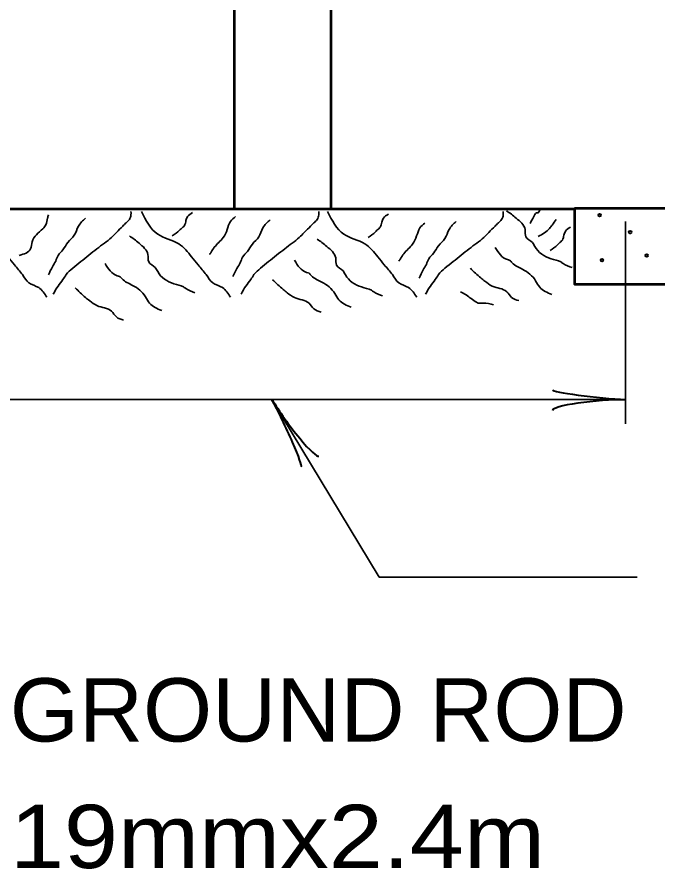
# Model space of a CAD drawing. Extents: x 14808 to 15663, y 10944 to 11488.
# Drawn here: x 14967.94 to 14998.34, y 11241.7 to 11282.09 of the extents above; entities that cross this region are included whole.
import ezdxf

# ---------------------------------------------------------------- set-up
doc = ezdxf.new("R2010")
doc.units = 0
doc.header["$LTSCALE"] = 1.2
doc.layers.add('1', color=7, linetype='Continuous', lineweight=53)

msp = doc.modelspace()

# ---------------------------------------------------------------- linework, layer by layer
at = {"layer": '1'}
for p, q in [((14978.258, 11273.001), (14978.258, 11294.621)), ((14982.845, 11273.001), (14982.845, 11294.621)), ((14963.259, 11273.001), (14994.385, 11273.001))]:
    msp.add_line(p, q, dxfattribs=at)
at = {"layer": '1', "lineweight": 35}
for p, q in [((14996.793, 11272.402), (14996.793, 11262.802)), ((14996.793, 11263.956), (14963.259, 11263.956))]:
    msp.add_line(p, q, dxfattribs=at)
at = {"layer": '1'}
for points in [[(14994.385, 11273.024), (15144.385, 11273.024), (15144.385, 11276.623), (15179.229, 11276.623)], [(14994.385, 11273.001), (14994.385, 11269.424), (15147.085, 11269.424), (15147.085, 11276.623)]]:
    msp.add_lwpolyline(points, dxfattribs=at)
at = {"layer": '1', "lineweight": 35}
msp.add_lwpolyline([(14980.026, 11263.956), (14985.125, 11255.533), (14997.359, 11255.533)], dxfattribs=at)
at = {"layer": '1', "lineweight": 40}
for centre in [(14995.572, 11272.697), (14997.022, 11271.892), (14995.689, 11270.559), (14997.805, 11270.781)]:
    msp.add_circle(centre, 0.06, dxfattribs=at)
for centre, major_axis, ratio, start_param, end_param in [((14995.449, 11264.21), (2.108, -0.211), 0.07063, 3.140715, 5.41811), ((14980.505, 11262.674), (-0.911, 1.912), 0.07063, 3.140715, 5.41811), ((14980.988, 11263.008), (-1.27, 1.736), 0.122415, 0.896353, 3.141593), ((14995.484, 11263.624), (2.143, 0.187), 0.122415, 0.896353, 3.141593)]:
    msp.add_ellipse(centre, major_axis=major_axis, ratio=ratio, start_param=start_param, end_param=end_param, dxfattribs=at)
at = {"layer": '1', "lineweight": 35}
for points in [[(14965.13, 11272.868), (14965.898, 11271.793), (14966.896, 11271.332), (14967.51, 11270.718), (14967.817, 11270.334), (14968.201, 11269.874), (14968.508, 11269.49), (14968.969, 11269.26), (14969.353, 11268.799)], [(14968.047, 11270.786), (14968.585, 11271.093), (14968.662, 11271.438), (14969.161, 11272.052), (14969.314, 11272.244), (14969.391, 11272.552), (14969.429, 11272.705)], [(14973.345, 11272.868), (14973.345, 11272.714), (14973.268, 11272.484), (14973.114, 11272.33), (14972.961, 11272.177), (14972.654, 11271.87), (14972.423, 11271.639), (14971.732, 11271.102), (14971.349, 11270.795), (14970.581, 11270.181), (14970.274, 11269.874), (14970.12, 11269.643), (14969.89, 11269.336), (14969.66, 11268.952)], [(14973.844, 11272.868), (14974.612, 11271.793), (14975.61, 11271.332), (14976.224, 11270.718), (14976.531, 11270.334), (14976.915, 11269.874), (14977.222, 11269.49), (14977.683, 11269.26), (14978.067, 11268.799)], [(14976.262, 11272.82), (14976.032, 11272.628), (14975.955, 11272.436), (14975.878, 11272.206), (14975.725, 11272.052), (14975.648, 11271.976), (14975.302, 11271.707)], [(14978.297, 11272.628), (14978.066, 11272.398), (14977.913, 11272.014), (14977.721, 11271.63), (14977.299, 11271.17), (14977.145, 11270.939), (14977.068, 11270.824)], [(14982.251, 11272.868), (14982.251, 11272.714), (14982.174, 11272.484), (14982.02, 11272.33), (14981.867, 11272.177), (14981.56, 11271.87), (14981.329, 11271.639), (14980.638, 11271.102), (14980.255, 11270.795), (14979.487, 11270.181), (14979.18, 11269.874), (14979.026, 11269.643), (14978.796, 11269.336), (14978.566, 11268.952)], [(14982.673, 11272.868), (14983.441, 11271.793), (14984.439, 11271.332), (14985.053, 11270.718), (14985.36, 11270.334), (14985.744, 11269.874), (14986.051, 11269.49), (14986.512, 11269.26), (14986.896, 11268.799)], [(14985.552, 11272.744), (14985.322, 11272.552), (14985.245, 11272.36), (14985.168, 11272.129), (14985.014, 11271.976), (14984.938, 11271.899), (14984.592, 11271.63)], [(14991.003, 11272.868), (14991.003, 11272.714), (14990.926, 11272.484), (14990.773, 11272.33), (14990.619, 11272.177), (14990.312, 11271.87), (14990.082, 11271.639), (14989.391, 11271.102), (14989.007, 11270.795), (14988.239, 11270.181), (14987.932, 11269.874), (14987.778, 11269.643), (14987.548, 11269.336), (14987.318, 11268.952)], [(14991.156, 11272.897), (14991.387, 11272.743), (14991.617, 11272.551), (14992.039, 11272.014), (14992.078, 11271.668), (14992.385, 11271.4), (14992.5, 11271.208), (14993.268, 11270.632), (14993.728, 11270.479), (14993.844, 11270.402), (14994.266, 11270.21)], [(14992.736, 11272.952), (14992.621, 11272.798), (14992.582, 11272.798), (14992.506, 11272.721), (14992.314, 11272.376), (14992.275, 11272.299)], [(14971.195, 11272.552), (14970.85, 11272.168), (14970.658, 11271.745), (14970.351, 11271.4), (14970.12, 11271.054), (14969.89, 11270.786), (14969.775, 11270.517), (14969.621, 11270.248), (14969.429, 11269.864)], [(14979.947, 11272.475), (14979.602, 11272.091), (14979.41, 11271.668), (14979.103, 11271.323), (14978.873, 11270.978), (14978.642, 11270.709), (14978.527, 11270.44), (14978.373, 11270.171), (14978.182, 11269.788)], [(14987.279, 11272.321), (14987.049, 11272.091), (14986.895, 11271.707), (14986.704, 11271.323), (14986.281, 11270.863), (14986.128, 11270.632), (14986.051, 11270.517)], [(14988.776, 11272.398), (14988.431, 11272.014), (14988.239, 11271.592), (14987.932, 11271.246), (14987.702, 11270.901), (14987.471, 11270.632), (14987.356, 11270.363), (14987.202, 11270.095), (14987.011, 11269.711)], [(14992.666, 11271.685), (14993.203, 11272.069), (14993.318, 11272.222), (14993.51, 11272.491)], [(14994.189, 11272.129), (14993.959, 11271.937), (14993.882, 11271.745), (14993.805, 11271.515), (14993.651, 11271.362), (14993.575, 11271.285), (14993.229, 11271.016)], [(14973.268, 11271.707), (14973.498, 11271.553), (14973.729, 11271.362), (14974.151, 11270.824), (14974.189, 11270.479), (14974.496, 11270.21), (14974.612, 11270.018), (14975.379, 11269.442), (14975.84, 11269.289), (14975.955, 11269.212), (14976.377, 11269.02)], [(14982.174, 11271.553), (14982.404, 11271.4), (14982.634, 11271.208), (14983.057, 11270.67), (14983.095, 11270.325), (14983.402, 11270.056), (14983.517, 11269.864), (14984.285, 11269.289), (14984.746, 11269.135), (14984.861, 11269.058), (14985.283, 11268.866)], [(14990.62, 11271.162), (14991.196, 11270.586), (14991.311, 11270.548), (14991.426, 11270.433), (14991.925, 11270.125), (14992.539, 11269.588), (14992.731, 11269.281), (14993.307, 11268.935)], [(14972.117, 11270.402), (14972.692, 11269.826), (14972.807, 11269.788), (14972.923, 11269.673), (14973.422, 11269.365), (14974.036, 11268.828), (14974.228, 11268.521), (14974.803, 11268.175)], [(14981.099, 11270.555), (14981.675, 11269.98), (14981.79, 11269.941), (14981.905, 11269.826), (14982.404, 11269.519), (14983.018, 11268.982), (14983.21, 11268.675), (14983.786, 11268.329)], [(14989.443, 11270.177), (14989.942, 11269.716), (14990.134, 11269.563), (14990.48, 11269.333), (14991.171, 11269.064), (14991.401, 11268.795), (14991.747, 11268.641)], [(14980.062, 11269.634), (14980.562, 11269.174), (14980.754, 11269.02), (14981.099, 11268.79), (14981.79, 11268.521), (14982.02, 11268.252), (14982.366, 11268.099)], [(14970.696, 11269.25), (14971.195, 11268.79), (14971.387, 11268.636), (14971.733, 11268.406), (14972.424, 11268.137), (14972.654, 11267.868), (14972.999, 11267.715)], [(14988.97, 11269.064), (14989.239, 11268.911), (14989.738, 11268.565), (14989.815, 11268.527), (14990.045, 11268.527), (14990.544, 11268.45)]]:
    msp.add_spline(points, degree=3, dxfattribs=at)

# ---------------------------------------------------------------- texts
at = {"layer": '1'}
for s, width, p in [('GROUND ROD', 1.05, (14967.6, 11247.74)), ('19mmx2.4m', 1.15, (14967.6, 11241.74))]:
    msp.add_text(s, height=3, dxfattribs=dict(at, width=width)).set_placement(p)

doc.saveas('drawing.dxf')
